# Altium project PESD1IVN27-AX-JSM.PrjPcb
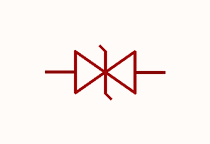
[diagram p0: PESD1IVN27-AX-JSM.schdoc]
1 sheet, 1 parts. Net scope: global (net labels, ports and power ports of the same name join across sheets).

## Sheet PESD1IVN27-AX-JSM.schdoc
size 127 x 101 mm

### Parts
D?  pesd1ivn27-ax-jsm  [SOD-323_L1.7-W1.3-LS2.7-BI]  (value not drawn)

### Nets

Not connected (* = marked no-connect by the designer): D? 1(C) 2(A)

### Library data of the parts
D? = pesd1ivn27-ax-jsm: 极性:-;反向截止电压(Vrwm):27V;钳位电压:50V;峰值脉冲电流(Ipp):3A@8/20us;峰值脉冲功率(Ppp):150W@8/20us;击穿电压(VBR):33.5V;; Manufacturer: JSMSEMI(杰盛微); AddInBom: yes; ModelId: dd567d373db645b3a267ff184369a271; ModelTransform: 102.362,50.197,0,0,0,0,0,0,0; Reverse Stand-Off Voltage (Vrwm): 27V; Clamping Voltage: 50V; Voltage - Breakdown: 33.5V; Reverse Leakage Current (Ir): 100nA; level of protection: IEC 61000-4-2; Type: ESD; Junction Capacitance: 15pF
